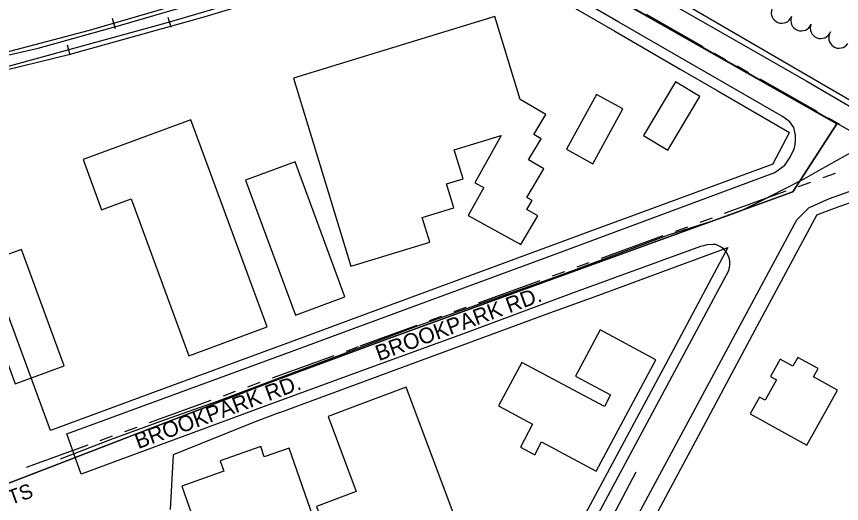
# Model space of a CAD drawing. Extents: x -25029 to 2274964, y -81170 to 687028.
# Drawn here: x -15076 to -14288, y -64109 to -63645 of the extents above; entities that cross this region are included whole.
import ezdxf

# ---------------------------------------------------------------- set-up
doc = ezdxf.new("R2010")
doc.units = 0
for name, color, linetype in [('81911BEA - RW_X_Fee_RW', 7, 'Continuous'), ('BD_X_Canopy', 7, 'Continuous'), ('BLDG', 7, 'Continuous'), ('DIVISIONS', 7, 'Continuous'), ('DV_X_Corp_Line', 7, 'Continuous'), ('GE_X_CL_100', 7, 'Continuous'), ('GE_X_CL_2000', 7, 'Continuous'), ('PV_X_EOP', 7, 'Continuous'), ('RD_X_RR_1', 7, 'Continuous'), ('ROAD', 7, 'Continuous'), ('ROAD-NAME', 7, 'Continuous'), ('RR', 7, 'Continuous'), ('TREES', 7, 'Continuous')]:
    doc.layers.add(name, color=color, linetype=linetype)

msp = doc.modelspace()

# ---------------------------------------------------------------- linework, layer by layer
at = {"layer": '81911BEA - RW_X_Fee_RW'}
for p, q in [((-14354.09, -63785.47), (-14337.89, -63755.29)), ((-15043.87, -64039.67), (-15136.87, -63787.3)), ((-14294.92, -63827.71), (-14238.21, -63806.89)), ((-14312.01, -63833.99), (-14294.92, -63827.71)), ((-14926.74, -64062.83), (-14929.54, -64114.95))]:
    msp.add_line(p, q, dxfattribs=at)
for points in [[(-14229.14, -63754.36), (-14430.66, -63637.33), (-14516, -63587.77), (-14618.75, -63528.1), (-14679.69, -63492.71), (-14713.28, -63473.2), (-14717.01, -63471.03)], [(-14776.7, -63501.12), (-14768.57, -63505.83), (-14561.36, -63625.98), (-14504.91, -63658.71), (-14442.58, -63694.85)], [(-14442.58, -63694.85), (-14407.21, -63715.27), (-14337.89, -63755.29)], [(-14354.09, -63785.47), (-14467.24, -63827.17), (-14523.79, -63848.01), (-14733.97, -63925.47), (-14809.04, -63953.13), (-14950.03, -64005.09), (-14978.18, -64015.46), (-15043.87, -64039.67)], [(-14312.01, -63833.99), (-14371.02, -63943.98), (-14413.57, -64023.29), (-14528.45, -64237.42)], [(-14824.93, -64022.41), (-14801.46, -64013.79), (-14707.59, -63979.3), (-14566.79, -63927.58), (-14523.75, -63911.77), (-14396.82, -63865.14)], [(-14396.82, -63865.14), (-14451.67, -63967.69), (-14584.03, -64214.44)], [(-14824.93, -64022.41), (-14848.29, -64031.32), (-14926.74, -64062.83)]]:
    msp.add_lwpolyline(points, dxfattribs=at)
at = {"layer": 'BD_X_Canopy'}
msp.add_line((-14484.78, -64079.31), (-14663.85, -64420.52), dxfattribs=at)
at = {"layer": 'BLDG'}
msp.add_line((-14748.36, -63880.42), (-14681.65, -63860.04), dxfattribs=at)
for points in [[(-14681.65, -63860.04), (-14688.88, -63836.37), (-14658.78, -63827.17), (-14665.71, -63804.48), (-14649.68, -63799.58), (-14658.16, -63771.82), (-14613.39, -63758.14), (-14638.52, -63803.25), (-14630.08, -63807.95), (-14644.81, -63834.4), (-14594.61, -63862.37), (-14578.42, -63834.82), (-14588.76, -63828.74), (-14583.83, -63820.36), (-14588.82, -63817.43), (-14572.73, -63790.07), (-14587.16, -63781.59), (-14575.27, -63761.36), (-14582.13, -63757.32), (-14570.9, -63738.21), (-14595.19, -63723.94), (-14619.39, -63644.73), (-14748.36, -63684.14)], [(-14748.36, -63684.14), (-14811.74, -63703.5), (-14756.88, -63883.03), (-14748.36, -63880.42)], [(-14748.36, -64188.9), (-14721.46, -64178.84), (-14728.74, -64159.35), (-14654.27, -64131.52), (-14704.02, -63998.39), (-14748.36, -64014.96)], [(-14748.36, -64014.96), (-14778.74, -64026.31), (-14751.97, -64097.96)], [(-14751.97, -64097.96), (-14789.75, -64112.07), (-14759.49, -64193.05), (-14748.36, -64188.9)]]:
    msp.add_lwpolyline(points, dxfattribs=at)
for points in [[(-14454.39, -63772.29), (-14423.59, -63720.98), (-14446.82, -63707.03), (-14477.62, -63758.35)], [(-14551.04, -63771.25), (-14525.72, -63785.12), (-14497.08, -63732.83), (-14522.4, -63718.96)], [(-14837.05, -63940.81), (-14909.92, -63743.18), (-15012.77, -63781.1), (-14995.04, -63829.19), (-14966.74, -63818.75), (-14911.6, -63968.3)], [(-14762.63, -63912.06), (-14810.17, -63783.4), (-14857.49, -63800.88), (-14809.95, -63929.55)], [(-15030.88, -63977.98), (-15071.49, -63866.88), (-15118.3, -63883.99), (-15077.69, -63995.09)], [(-14542.53, -63987.78), (-14508.89, -64005.78), (-14514.85, -64016.92), (-14593.76, -63974.71), (-14615.95, -64016.2), (-14583.36, -64033.63), (-14595.08, -64055.54), (-14581.36, -64062.89), (-14574.76, -64050.56), (-14522.69, -64078.42), (-14465.85, -63972.16), (-14518.98, -63943.74)], [(-14315.16, -63988.5), (-14310.8, -63980.6), (-14330.1, -63969.97), (-14334.77, -63978.43), (-14347.05, -63971.66), (-14356.16, -63988.19), (-14350.56, -63991.28), (-14361.31, -64010.79), (-14366.7, -64007.82), (-14375.55, -64023.88), (-14321.35, -64053.75), (-14292.33, -64001.09)], [(-14839.66, -64064.75), (-14843.06, -64055.01), (-14881.75, -64068.51), (-14878.21, -64078.65), (-14918.43, -64092.69), (-14896.16, -64156.52), (-14816.68, -64128.78), (-14801.11, -64173.37), (-14777.94, -64165.29), (-14815.92, -64056.47)]]:
    msp.add_lwpolyline(points, close=True, dxfattribs=at)
at = {"layer": 'DIVISIONS'}
for p, q in [((-14475.08, -63642.46), (-14420.73, -63673.33)), ((-14409.87, -63679.5), (-14399, -63685.68)), ((-14388.13, -63691.85), (-14377.26, -63698.02)), ((-14366.39, -63704.2), (-14312.05, -63735.07)), ((-14301.18, -63741.24), (-14290.31, -63747.42)), ((-14294.54, -63794.38), (-14306.29, -63798.64)), ((-14318.04, -63802.91), (-14329.79, -63807.18)), ((-14341.54, -63811.44), (-14400.29, -63832.77)), ((-14412.04, -63837.04), (-14423.79, -63841.31)), ((-14435.53, -63845.57), (-14447.28, -63849.84)), ((-14459.03, -63854.11), (-14517.78, -63875.44)), ((-14529.53, -63879.7), (-14541.28, -63883.97)), ((-14553.03, -63888.24), (-14564.78, -63892.5)), ((-14576.53, -63896.77), (-14635.28, -63918.1)), ((-14647.02, -63922.37), (-14658.77, -63926.63)), ((-14670.52, -63930.9), (-14682.27, -63935.16)), ((-14694.02, -63939.43), (-14748.36, -63959.16)), ((-14761.28, -63963.85), (-14749.53, -63959.58)), ((-14831.77, -63989.45), (-14773.02, -63968.12)), ((-14855.27, -63997.98), (-14843.52, -63993.71)), ((-14878.77, -64006.51), (-14867.02, -64002.24)), ((-14949.27, -64032.11), (-14890.52, -64010.78)), ((-14972.77, -64040.64), (-14961.02, -64036.37)), ((-14996.26, -64049.17), (-14984.52, -64044.91)), ((-15066.76, -64074.77), (-15008.01, -64053.44))]:
    msp.add_line(p, q, dxfattribs=at)
at = {"layer": 'DV_X_Corp_Line'}
for p, q in [((-14292.76, -63747.06), (-14755.02, -63485.11)), ((-14292.76, -63747.06), (-14755.02, -63485.11)), ((-14755.02, -63485.11), (-14292.76, -63747.06)), ((-14755.02, -63485.11), (-14292.76, -63747.06)), ((-14334.94, -63812.09), (-14292.76, -63747.06)), ((-14334.94, -63812.09), (-14292.76, -63747.06)), ((-14292.76, -63747.06), (-14334.94, -63812.09)), ((-14292.76, -63747.06), (-14334.94, -63812.09)), ((-14718.04, -63950.88), (-14334.94, -63812.09)), ((-14718.04, -63950.88), (-14334.94, -63812.09)), ((-14334.94, -63812.09), (-14718.04, -63950.88)), ((-14334.94, -63812.09), (-14718.04, -63950.88)), ((-14835.33, -63994.09), (-14718.04, -63950.88)), ((-14835.33, -63994.09), (-14718.04, -63950.88)), ((-14718.04, -63950.88), (-14835.33, -63994.09)), ((-14718.04, -63950.88), (-14835.33, -63994.09)), ((-15130.61, -64108.1), (-14835.33, -63994.09)), ((-15130.61, -64108.1), (-14835.33, -63994.09)), ((-14835.33, -63994.09), (-15130.61, -64108.1)), ((-14835.33, -63994.09), (-15130.61, -64108.1))]:
    msp.add_line(p, q, dxfattribs=at)
at = {"layer": 'GE_X_CL_2000'}
for points in [[(-14261.06, -63764.66), (-14341.58, -63719.13), (-14458.54, -63652.57), (-14554.3, -63598.62), (-14589.72, -63575.95), (-14679.25, -63534.31), (-14714.87, -63510.28), (-14749.74, -63489.42)], [(-14261.06, -63764.66), (-14277.04, -63773.21), (-14292.94, -63781.94), (-14308.73, -63790.85), (-14324.43, -63799.93)], [(-14324.43, -63799.93), (-14344.24, -63810.15), (-14364.14, -63820.18), (-14384.12, -63830.04), (-14397.97, -63835.07), (-14411.9, -63839.89), (-14425.89, -63844.53), (-14439.95, -63848.97), (-14454.07, -63853.22), (-14557.89, -63892.09), (-14696.15, -63940.96), (-14884.71, -64012.03), (-14935.13, -64029.96), (-14972.88, -64043.57), (-14984.33, -64047.64), (-15034.67, -64066.97)]]:
    msp.add_lwpolyline(points, dxfattribs=at)
at = {"layer": 'PV_X_EOP'}
for p, q in [((-14331.14, -63838.57), (-14318.9, -63826.67)), ((-14573.3, -64288.69), (-14331.14, -63838.57)), ((-14594.42, -64256), (-14396.24, -63887.62))]:
    msp.add_line(p, q, dxfattribs=at)
for points in [[(-12974.21, -64521.01), (-13160.63, -64414.95), (-13303.62, -64332.46), (-13426.26, -64262.89), (-13565.4, -64181.4), (-13676.76, -64118.75), (-13804.8, -64044.31), (-13932.59, -63970.77), (-14081.11, -63885.48), (-14217.35, -63808.45), (-14234.35, -63802.92), (-14245.26, -63802.15), (-14254.14, -63802.69), (-14262.47, -63805.44), (-14300.2, -63818.7), (-14318.74, -63827.02)], [(-14403.25, -63864.73), (-14408.38, -63862.27), (-14411.36, -63862.09), (-14416.59, -63862.49), (-14420.07, -63863.44), (-14422.93, -63864.23), (-14546.26, -63909.1), (-14644.32, -63945.67), (-14748.36, -63983.53)]]:
    msp.add_lwpolyline(points, dxfattribs=at)
msp.add_arc((-14414.03, -63880.55), 19.14, 338.33067, 55.71884, dxfattribs=at)
at = {"layer": 'RD_X_RR_1'}
for points in [[(-15597.33, -63804.3), (-15486.73, -63779.84), (-15399.59, -63760.09), (-15325.16, -63742.41), (-15245.16, -63722.45), (-15152.68, -63699.31), (-15084.77, -63681.44), (-15055.64, -63674.98), (-14975.57, -63652.46), (-14863.25, -63619.67), (-14785.87, -63596.21), (-14696.17, -63569.06)], [(-15582.62, -63815.24), (-15463.95, -63788.4), (-15326.8, -63755.84), (-15225.43, -63730.69), (-15086.16, -63695.57), (-15025.08, -63680.75), (-14896.94, -63645), (-14754.62, -63601.61), (-14680.57, -63577.77)]]:
    msp.add_lwpolyline(points, dxfattribs=at)
at = {"layer": 'ROAD'}
for points in [[(-14748.36, -63940.17), (-14553.38, -63868.37), (-14351.89, -63793.56), (-14342.61, -63786.49), (-14337.96, -63779.95), (-14333.68, -63771.36), (-14332.49, -63766.9), (-14332.33, -63762.44), (-14332.38, -63757.79), (-14333.77, -63750.73), (-14337.87, -63745.05), (-14344.78, -63739.94), (-14501.18, -63650.05), (-14608.91, -63587.53), (-14725.75, -63524.14), (-14748.36, -63511.46)], [(-14507.86, -63599.81), (-14321.62, -63706.51), (-14194.84, -63780.38), (-14039.01, -63869.68), (-13913.51, -63945.01), (-13801.56, -64010.73), (-13799.3, -64010.47), (-13794.87, -64008.33), (-13790.87, -64005.06), (-13788.44, -64002.32), (-13783.98, -63996.08), (-13780.92, -63989.69), (-13780.15, -63985.74), (-13779.73, -63982.92), (-13789.66, -63782.36), (-13792.64, -63630.55)], [(-14748.36, -63983.53), (-14839.9, -64016.84), (-15014.47, -64081.34), (-15028.2, -64042.76), (-14819.03, -63966.2), (-14748.36, -63940.17)]]:
    msp.add_lwpolyline(points, dxfattribs=at)
at = {"layer": 'RR'}
for p, q in [((-14984.89, -63646.41), (-14982.09, -63656.02)), ((-14931.72, -63645.32), (-14928.9, -63654.91)), ((-15028.06, -63671.74), (-15025.43, -63681.38))]:
    msp.add_line(p, q, dxfattribs=at)
for points in [[(-14748.36, -63582.76), (-15006.77, -63657.99), (-15234.37, -63717.71), (-15355.01, -63747.07)], [(-14748.36, -63596.6), (-14933.72, -63651.12), (-15146.03, -63709.18), (-15354.47, -63761.06)]]:
    msp.add_lwpolyline(points, dxfattribs=at)
at = {"layer": 'TREES'}
for centre, start, end in [((-14345.45, -63641.08), 158.56808, 338.56808), ((-14326.83, -63648.39), 158.56808, 338.56808), ((-14308.22, -63655.7), 158.56808, 338.56808), ((-14290.59, -63664.9), 146.3014, 326.3014)]:
    msp.add_arc(centre, 10, start, end, dxfattribs=at)

# ---------------------------------------------------------------- texts
at = {"layer": 'GE_X_CL_100'}
msp.add_text('BROOKLYN HEIGHTS', height=14, rotation=19.79643, dxfattribs=at).set_placement((-15240.27, -64168.05))
at = {"layer": 'ROAD-NAME'}
for p in [(-14730.22, -63973.62), (-14960.1, -64057.53)]:
    msp.add_text('BROOKPARK RD.', height=15, rotation=20.14675, dxfattribs=at).set_placement(p)

doc.saveas('drawing.dxf')
